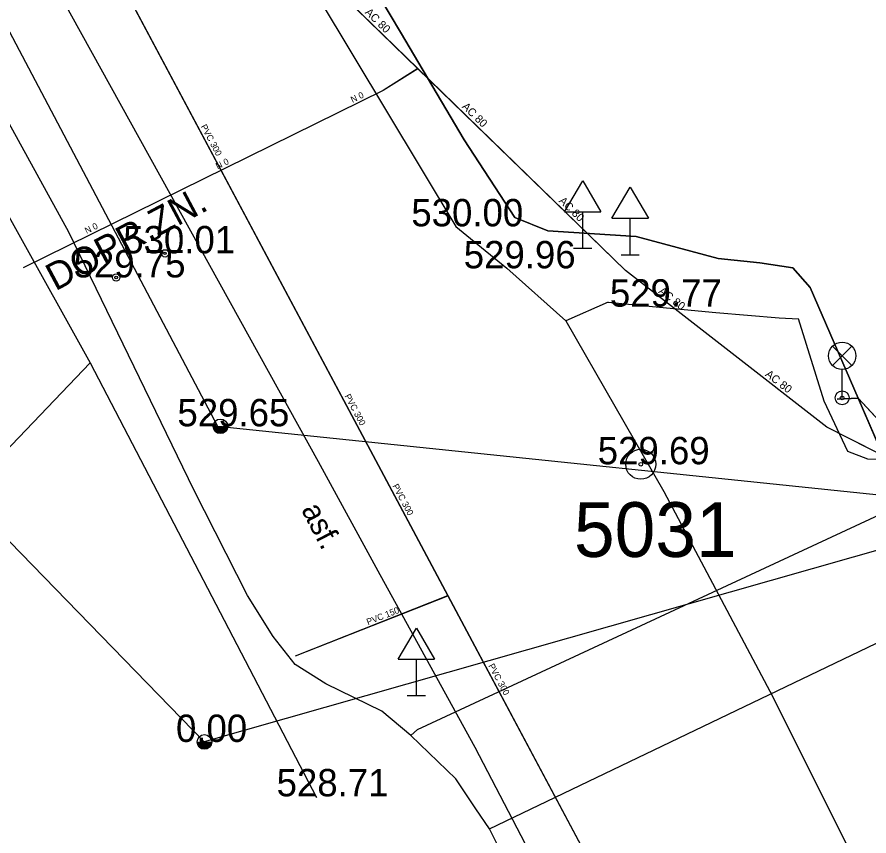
# Model space of a CAD drawing. Extents: x -669393 to -668650, y -1126925 to -1126294.
# Drawn here: x -669014.21 to -668990.85, y -1126799.71 to -1126777.26 of the extents above; entities that cross this region are included whole.
import ezdxf

# ---------------------------------------------------------------- set-up
doc = ezdxf.new("R2010")
doc.units = 0
for name, color, linetype in [('G_Bod_tecka', 7, 'Continuous'), ('G_Bod_vyska', 7, 'Continuous'), ('G_Bodove_pole', 7, 'Continuous'), ('G_Cesty_Schody', 7, 'Continuous'), ('G_Objekty_dopravni', 7, 'Continuous'), ('G_Objekty_technicke', 7, 'Continuous'), ('G_Plochy_zpevnene', 7, 'Continuous'), ('G_Ploty', 7, 'Continuous'), ('G_Popisy_povrchu', 7, 'Continuous'), ('G_Poznamky_odkaz', 7, 'Continuous'), ('G_Site-Sloupy', 7, 'Continuous'), ('G_Z_ELsilove_nadz_kotovane', 7, 'Continuous'), ('G_Z_ELsilove_podz_kotovane', 7, 'Continuous'), ('G_Z_KANAL_podz_kotovane', 7, 'Continuous'), ('G_Z_SPOJE_podz_geodeticky', 7, 'Continuous'), ('G_Z_SPOJE_podz_kotovane', 7, 'Continuous'), ('G_Z_SPOJE_podz_priblizne', 7, 'Continuous'), ('G_Z_VODA_podz_kotovane', 7, 'Continuous'), ('G_Zelen-okraj', 7, 'Continuous'), ('Vrstva 1', 7, 'Continuous'), ('Vrstva 12', 7, 'Continuous'), ('Vrstva 13', 7, 'Continuous'), ('Vrstva 25', 7, 'Continuous'), ('Vrstva 27', 7, 'Continuous'), ('Vrstva 3', 7, 'Continuous'), ('Vrstva 4', 7, 'Continuous'), ('Vrstva 6', 7, 'Continuous'), ('Vrstva 62', 7, 'Continuous')]:
    doc.layers.add(name, color=color, linetype=linetype)

msp = doc.modelspace()

# ---------------------------------------------------------------- linework, layer by layer
at = {"layer": 'G_Bod_tecka'}
for p, q in [((-669002.18, -1126783), (-669002.18, -1126783)), ((-669010.15, -1126783.74), (-669010.15, -1126783.74)), ((-669000.78, -1126784.15), (-669000.78, -1126784.15)), ((-669011.49, -1126784.4), (-669011.49, -1126784.4)), ((-668996.79, -1126785.2), (-668996.79, -1126785.2)), ((-669008.63, -1126788.48), (-669008.63, -1126788.48)), ((-668997.11, -1126789.52), (-668997.11, -1126789.52)), ((-669009.07, -1126797.13), (-669009.07, -1126797.13)), ((-669005.99, -1126798.62), (-669005.99, -1126798.62))]:
    msp.add_line(p, q, dxfattribs=at)
at = {"layer": 'G_Bodove_pole'}
for radius in [0.412, 0.05]:
    msp.add_circle((-668997.11, -1126789.52), radius, dxfattribs=at)
at = {"layer": 'G_Cesty_Schody'}
for p, q in [((-668999.16, -1126785.59), (-668996.48, -1126790.27)), ((-668996.48, -1126790.27), (-668993.49, -1126795.89)), ((-668993.49, -1126795.89), (-668990.9, -1126801.08))]:
    msp.add_line(p, q, dxfattribs=at)
at = {"layer": 'G_Objekty_dopravni'}
for p, q in [((-668999.2, -1126782.6), (-668998.7, -1126781.75)), ((-668998.7, -1126781.75), (-668998.2, -1126782.6)), ((-668997.9, -1126782.78), (-668997.4, -1126781.93)), ((-668997.4, -1126781.93), (-668996.9, -1126782.78)), ((-668999.2, -1126782.6), (-668998.2, -1126782.6)), ((-668998.7, -1126783.6), (-668998.7, -1126782.6)), ((-668997.9, -1126782.78), (-668996.9, -1126782.78)), ((-668997.4, -1126783.78), (-668997.4, -1126782.78)), ((-668998.95, -1126783.6), (-668998.45, -1126783.6)), ((-668997.65, -1126783.78), (-668997.15, -1126783.78)), ((-669003.76, -1126794.86), (-669003.26, -1126794.01)), ((-669003.26, -1126794.01), (-669002.76, -1126794.86)), ((-669003.76, -1126794.86), (-669002.76, -1126794.86)), ((-669003.26, -1126795.86), (-669003.26, -1126794.86)), ((-669003.51, -1126795.86), (-669003.01, -1126795.86))]:
    msp.add_line(p, q, dxfattribs=at)
at = {"layer": 'G_Objekty_technicke'}
for p, q in [((-668991.855, -1126786.285), (-668991.325, -1126786.815)), ((-668991.855, -1126786.815), (-668991.325, -1126786.285)), ((-668991.59, -1126787.7), (-668991.59, -1126786.925))]:
    msp.add_line(p, q, dxfattribs=at)
for centre, radius in [((-668991.59, -1126786.55), 0.375), ((-668991.59, -1126787.7), 0.19), ((-668991.59, -1126787.7), 0.05)]:
    msp.add_circle(centre, radius, dxfattribs=at)
at = {"layer": 'G_Plochy_zpevnene'}
for p, q in [((-669012.39, -1126766), (-669002.18, -1126783)), ((-669005.94, -1126789.45), (-669016.35, -1126770.66)), ((-669004.25, -1126792.55), (-669005.94, -1126789.45))]:
    msp.add_line(p, q, dxfattribs=at)
for points in [[(-669002.18, -1126783), (-669001.48, -1126783.58), (-669000.78, -1126784.15)], [(-668998, -1126785.08), (-668999.16, -1126785.59), (-669000.78, -1126784.15)], [(-668998, -1126785.08), (-668996.79, -1126785.2), (-668995.05, -1126785.36), (-668993.32, -1126785.51), (-668992.79, -1126785.53)], [(-668987.57, -1126789.52), (-668989.93, -1126789.4), (-668990.89, -1126789.38), (-668991.43, -1126789.17), (-668992.08, -1126787.79), (-668992.79, -1126785.53)], [(-668999.58, -1126801.25), (-669001.65, -1126797.28), (-669004.25, -1126792.55)]]:
    msp.add_lwpolyline(points, dxfattribs=at)
at = {"layer": 'G_Ploty'}
msp.add_lwpolyline([(-669020.49, -1126771.84), (-669012.2, -1126786.74), (-669006, -1126798.65)], dxfattribs=at)
at = {"layer": 'G_Site-Sloupy'}
for centre, radius in [((-669010.15, -1126783.74), 0.1), ((-669010.15, -1126783.74), 0.0348), ((-669011.49, -1126784.4), 0.1), ((-669011.49, -1126784.4), 0.0348), ((-669008.63, -1126788.48), 0.2), ((-669009.07, -1126797.13), 0.2)]:
    msp.add_circle(centre, radius, dxfattribs=at)
for centre, radius in [((-669008.63, -1126788.48), 0.18), ((-669008.63, -1126788.48), 0.16), ((-669008.63, -1126788.48), 0.14), ((-669008.63, -1126788.48), 0.12), ((-669008.63, -1126788.48), 0.1), ((-669008.63, -1126788.48), 0.08), ((-669008.63, -1126788.48), 0.06), ((-669008.63, -1126788.48), 0.04), ((-669008.63, -1126788.48), 0.02), ((-669009.07, -1126797.13), 0.18), ((-669009.07, -1126797.13), 0.16), ((-669009.07, -1126797.13), 0.14), ((-669009.07, -1126797.13), 0.12), ((-669009.07, -1126797.13), 0.1), ((-669009.07, -1126797.13), 0.08), ((-669009.07, -1126797.13), 0.06), ((-669009.07, -1126797.13), 0.04), ((-669009.07, -1126797.13), 0.02)]:
    msp.add_arc(centre, radius, 180, 0, dxfattribs=at)
at = {"layer": 'G_Z_ELsilove_nadz_kotovane'}
for points in [[(-669067.24, -1126693.43), (-669054.01, -1126713.61), (-669038.28, -1126736.27), (-669025.74, -1126756.2), (-669008.71, -1126788.48), (-668986.7, -1126790.76)], [(-668987.976, -1126791.123), (-669009.08, -1126797.13), (-669028.53, -1126777.12), (-669049.9, -1126757.02)]]:
    msp.add_lwpolyline(points, dxfattribs=at)
at = {"layer": 'G_Z_ELsilove_podz_kotovane'}
for points in [[(-668991.15, -1126787.71), (-668992.47, -1126784.68), (-668992.94, -1126784.14), (-668993.85, -1126784), (-668994.99, -1126783.88), (-668997.24, -1126783.28), (-668999.66, -1126783.12), (-669000.56, -1126782.76), (-669001.95, -1126780.63), (-669003.7, -1126777.68), (-669006.31, -1126773.26), (-669007.38, -1126772.1), (-669009.06, -1126769.68), (-669009.55, -1126768.64), (-669025.04, -1126740.9), (-669039.34, -1126713.66), (-669057.59, -1126688.86), (-669057.53, -1126686.66), (-669073.8, -1126662.04), (-669088.6, -1126634.97), (-669111.98, -1126614.96), (-669163.86, -1126582.84), (-669189.05, -1126566.12), (-669226.41, -1126541.64)], [(-668991.15, -1126787.71), (-668991.73, -1126787.74)], [(-668986.31, -1126798.78), (-668989.31, -1126791.96), (-668991.15, -1126787.71)], [(-668991.15, -1126787.71), (-668988.62, -1126790.44), (-668986.81, -1126790.89)]]:
    msp.add_lwpolyline(points, dxfattribs=at)
at = {"layer": 'G_Z_KANAL_podz_kotovane'}
msp.add_line((-669006.57, -1126794.77), (-669002.4, -1126793.12), dxfattribs=at)
msp.add_lwpolyline([(-669021.5, -1126757.31), (-669019.78, -1126760.55), (-669002.4, -1126793.12), (-668998.38, -1126800.66), (-668997.87, -1126801.61)], dxfattribs=at)
at = {"layer": 'G_Z_SPOJE_podz_geodeticky'}
for points in [[(-669007.89, -1126793.12), (-669009.36, -1126790.22), (-669012.79, -1126783.16), (-669020.41, -1126769.29), (-669030.03, -1126751.08), (-669030.23, -1126750.3)], [(-669003.41, -1126796.95), (-669003.23, -1126796.79), (-668987.18, -1126789.33), (-668986.3, -1126788.65), (-668980.39, -1126785.93), (-668978.6, -1126785.68)], [(-669001.26, -1126799.51), (-668985.7, -1126792.05), (-668978.6, -1126785.68)], [(-669003.41, -1126796.95), (-669004.21, -1126796.29), (-669005.74, -1126795.54), (-669006.58, -1126795.01), (-669007.19, -1126794.24), (-669007.89, -1126793.12)], [(-669001.63, -1126798.96), (-669002.18, -1126798.14), (-669003.41, -1126796.95)], [(-669000.63, -1126800.94), (-669000.81, -1126800.41), (-669001.26, -1126799.51), (-669001.63, -1126798.96)]]:
    msp.add_lwpolyline(points, dxfattribs=at)
at = {"layer": 'G_Z_SPOJE_podz_kotovane'}
for points in [[(-669003.41, -1126796.95), (-669003.23, -1126796.79), (-668987.18, -1126789.33), (-668986.3, -1126788.65), (-668980.39, -1126785.93), (-668978.6, -1126785.68)], [(-669001.26, -1126799.51), (-668985.7, -1126792.05), (-668978.6, -1126785.68)]]:
    msp.add_lwpolyline(points, dxfattribs=at)
at = {"layer": 'G_Z_SPOJE_podz_priblizne'}
for points in [[(-669003.41, -1126796.95), (-669003.23, -1126796.79), (-668987.18, -1126789.33), (-668986.3, -1126788.65), (-668980.39, -1126785.93), (-668978.6, -1126785.68)], [(-669001.26, -1126799.51), (-668985.7, -1126792.05), (-668978.6, -1126785.68)]]:
    msp.add_lwpolyline(points, dxfattribs=at)
at = {"layer": 'G_Z_VODA_podz_kotovane'}
for points in [[(-668985.62, -1126791.74), (-668992.01, -1126788.5), (-668997.53, -1126784.21), (-669003.22, -1126778.68), (-669006.93, -1126775.07), (-669009.78, -1126769.85), (-669016.27, -1126757.96), (-669026.17, -1126739.37), (-669033.16, -1126727.07), (-669036.74, -1126721.2), (-669037.32, -1126720.23), (-669038.2, -1126718.75), (-669038.67, -1126717.89)], [(-669003.22, -1126778.68), (-669004.17, -1126779.28), (-669014.04, -1126784.14)]]:
    msp.add_lwpolyline(points, dxfattribs=at)
at = {"layer": 'G_Zelen-okraj'}
msp.add_line((-669015.96, -1126790.67), (-669012.2, -1126786.74), dxfattribs=at)
at = {"layer": 'Vrstva 1'}
msp.add_line((-668991.73, -1126787.74), (-668991.73, -1126787.74), dxfattribs=at)
at = {"layer": 'Vrstva 12'}
msp.add_lwpolyline([(-669021.5, -1126757.31), (-669019.78, -1126760.55), (-669002.4, -1126793.125), (-668998.377, -1126800.659), (-668997.87, -1126801.61)], dxfattribs=at)
at = {"layer": 'Vrstva 13'}
msp.add_line((-669006.57, -1126794.77), (-669002.4, -1126793.125), dxfattribs=at)
at = {"layer": 'Vrstva 25'}
msp.add_lwpolyline([(-669003.219, -1126778.678), (-669004.174, -1126779.276), (-669014.042, -1126784.139)], dxfattribs=at)
at = {"layer": 'Vrstva 27'}
msp.add_lwpolyline([(-668985.623, -1126791.742), (-668992.014, -1126788.499), (-668997.526, -1126784.214), (-669003.219, -1126778.678), (-669006.931, -1126775.068), (-669009.778, -1126769.852), (-669016.269, -1126757.96), (-669026.168, -1126739.368), (-669033.16, -1126727.07), (-669036.741, -1126721.201), (-669037.32, -1126720.228), (-669038.2, -1126718.75), (-669038.665, -1126717.892)], dxfattribs=at)
at = {"layer": 'Vrstva 6'}
msp.add_line((-669004.174, -1126779.276), (-669004.174, -1126779.276), dxfattribs=at)
at = {"layer": 'Vrstva 62'}
for p, q in [((-669003.7, -1126777.68), (-669006.31, -1126773.26)), ((-669006.31, -1126773.26), (-669003.7, -1126777.68)), ((-669001.95, -1126780.63), (-669003.7, -1126777.68)), ((-669003.7, -1126777.68), (-669001.95, -1126780.63)), ((-669000.56, -1126782.76), (-669001.95, -1126780.63)), ((-669001.95, -1126780.63), (-669000.56, -1126782.76)), ((-668999.66, -1126783.12), (-669000.56, -1126782.76)), ((-669000.56, -1126782.76), (-668999.66, -1126783.12)), ((-668997.24, -1126783.28), (-668999.66, -1126783.12)), ((-668999.66, -1126783.12), (-668997.24, -1126783.28)), ((-668994.99, -1126783.88), (-668997.24, -1126783.28)), ((-668997.24, -1126783.28), (-668994.99, -1126783.88)), ((-668993.85, -1126784), (-668994.99, -1126783.88)), ((-668994.99, -1126783.88), (-668993.85, -1126784)), ((-668992.94, -1126784.14), (-668993.85, -1126784)), ((-668993.85, -1126784), (-668992.94, -1126784.14)), ((-668992.47, -1126784.68), (-668992.94, -1126784.14)), ((-668992.94, -1126784.14), (-668992.47, -1126784.68)), ((-668991.155, -1126787.71), (-668992.47, -1126784.68)), ((-668992.47, -1126784.68), (-668991.155, -1126787.71)), ((-668991.155, -1126787.71), (-668991.73, -1126787.74)), ((-668991.73, -1126787.74), (-668991.155, -1126787.71)), ((-668989.31, -1126791.96), (-668991.155, -1126787.71)), ((-668991.155, -1126787.71), (-668988.621, -1126790.439)), ((-668988.621, -1126790.439), (-668991.155, -1126787.71)), ((-668991.155, -1126787.71), (-668989.31, -1126791.96))]:
    msp.add_line(p, q, dxfattribs=at)

# ---------------------------------------------------------------- texts
at = {"layer": 'G_Bod_vyska'}
for s, p in [('530.00', (-669003.399, -1126783)), ('530.01', (-669011.296, -1126783.74)), ('529.96', (-669001.962, -1126784.15)), ('529.75', (-669012.656, -1126784.4)), ('529.77', (-668997.956, -1126785.2)), ('529.65', (-669009.81, -1126788.48)), ('529.69', (-668998.289, -1126789.52)), ('0.00', (-669009.85, -1126797.13)), ('528.71', (-669007.092, -1126798.62))]:
    msp.add_text(s, height=0.75, dxfattribs=at).set_placement(p)
at = {"layer": 'G_Bodove_pole'}
msp.add_text('5031', height=1.5, dxfattribs=at).set_placement((-668998.942, -1126792.06))
at = {"layer": 'G_Popisy_povrchu'}
msp.add_text('asf.', height=0.6, rotation=297.4808, dxfattribs=at).set_placement((-669006.426, -1126790.764))
at = {"layer": 'G_Poznamky_odkaz'}
msp.add_text('DOPR.ZN.', height=0.75, rotation=28.0387, dxfattribs=at).set_placement((-669013.155, -1126784.785))
at = {"layer": 'Vrstva 3'}
for s, rotation, p in [('PVC 300', 298.0705, (-669009.178, -1126780.262)), ('PVC 300', 298.0705, (-669005.236, -1126787.651)), ('PVC 300', 298.0705, (-669003.923, -1126790.115)), ('PVC 150', 21.5551, (-669004.586, -1126793.931)), ('PVC 300', 298.0705, (-669001.294, -1126795.041))]:
    msp.add_text(s, height=0.1755, rotation=rotation, dxfattribs=at).set_placement(p)
at = {"layer": 'Vrstva 4'}
for s, height, rotation, p in [('AC 80', 0.2194, 315.7384, (-669004.686, -1126777.153)), ('N 0', 0.1755, 26.2695, (-669005.009, -1126779.619)), ('AC 80', 0.2194, 315.7384, (-669002.028, -1126779.737)), ('N 0', 0.1755, 26.159, (-669008.708, -1126781.442)), ('AC 80', 0.2194, 315.7384, (-668999.371, -1126782.321)), ('N 0', 0.1755, 26.1954, (-669012.298, -1126783.211)), ('AC 80', 0.2194, 322.1793, (-668996.642, -1126784.812)), ('AC 80', 0.2194, 322.1793, (-668993.716, -1126787.087))]:
    msp.add_text(s, height=height, rotation=rotation, dxfattribs=at).set_placement(p)

doc.saveas('drawing.dxf')
